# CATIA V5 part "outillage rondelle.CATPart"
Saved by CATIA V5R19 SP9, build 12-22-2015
Part number: outillage rondelle
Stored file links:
  D:\filesystem\herve.bezard\Telechargements\fausse table rondelle\outillage rondelle.CATPart
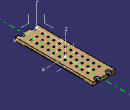
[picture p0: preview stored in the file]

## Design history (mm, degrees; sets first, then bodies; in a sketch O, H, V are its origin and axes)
AxisSystem1: origin (0, 0, 0), X (1, 0, 0), Y (0, 1, 0), Z (0, 0, 1)
AxisSystem2: origin (-48.5, -174, 0), X (1, 0, 0), Y (0, 1, 0), Z (0, 0, 1)
Set1 "GEOCN"
  Point1: (0, -3, 0), relative to vertex [face of Pad1 from Sketch1.L3 | face of Pad1 from Sketch1.L2 | start face of Pad1], in AxisSystem1
Body1 (main body)
  Sketch1 on XY plane of AxisSystem1, origin (0, 0, 0), H (1, 0, 0), V (0, 1, 0)
    line L1 (48.5, 171) -> (48.5, -171)
    line L2 (48.5, -171) -> (-48.5, -171)
    line L3 (-48.5, -171) -> (-48.5, 171)
    line L4 (-48.5, 171) -> (48.5, 171)
    distance L3 L1 = 97
    distance L4 L2 = 342
    vertical: L1 V, L3 V
    horizontal: L2 H, L4 H
    equidistance: L1 L3 O, L2 L4 O
  Pad1: profile Sketch1, direction (0, 0, 1), length 15
  Sketch2 on XY plane of AxisSystem1, origin (0, 0, 0), H (1, 0, 0), V (0, 1, 0)
    construction line L1 (-25, 173) -> (-25, 165)
    point P2 (-25, 165)
    line L2 (-21.9, 173) -> (-21.9, 165)
    line L3 (-28.1, 165) -> (-28.1, 173)
    arc A1 centre (-25, 165) radius 3.1 from (-21.9, 165) to (-28.1, 165) cw
    arc A2 centre (-25, 173) radius 3.1 from (-28.1, 173) to (-21.9, 173) cw
    construction line L4 (25, 173) -> (25, 165)
    point P8 (25, 165)
    line L5 (28.1, 173) -> (28.1, 165)
    line L6 (21.9, 165) -> (21.9, 173)
    arc A3 centre (25, 165) radius 3.1 from (28.1, 165) to (21.9, 165) cw
    arc A4 centre (25, 173) radius 3.1 from (21.9, 173) to (28.1, 173) cw
    construction line L7 (-25, -165) -> (-25, -173)
    point P13 (-25, -165)
    line L8 (-21.9, -165) -> (-21.9, -173)
    line L9 (-28.1, -173) -> (-28.1, -165)
    arc A5 centre (-25, -173) radius 3.1 from (-21.9, -173) to (-28.1, -173) cw
    arc A6 centre (-25, -165) radius 3.1 from (-28.1, -165) to (-21.9, -165) cw
    construction line L10 (25, -165) -> (25, -173)
    point P19 (25, -165)
    line L11 (28.1, -165) -> (28.1, -173)
    line L12 (21.9, -173) -> (21.9, -165)
    arc A7 centre (25, -173) radius 3.1 from (28.1, -173) to (21.9, -173) cw
    arc A8 centre (25, -165) radius 3.1 from (21.9, -165) to (28.1, -165) cw
    reference projected line E1 through (0, 0) direction (0, 1) from edge [YZ plane of AxisSystem1 | XY plane of AxisSystem1]
    reference projected line E2 through (0, 0) direction (0, 1) from edge [YZ plane of AxisSystem1 | XY plane of AxisSystem1]
    reference projected line E3 through (0, 0) direction (0, 1) from edge [YZ plane of AxisSystem1 | XY plane of AxisSystem1]
    reference projected line E4 through (0, 0) direction (0, 1) from edge [YZ plane of AxisSystem1 | XY plane of AxisSystem1]
    reference intersected line E5 (-48.5, 171) -> (48.5, 171) from face of Pad1 from Sketch1.L4
    reference intersected line E6 (-48.5, 171) -> (48.5, 171) from face of Pad1 from Sketch1.L4
    reference intersected line E7 (48.5, -171) -> (-48.5, -171) from face of Pad1 from Sketch1.L2
    reference intersected line E8 (48.5, -171) -> (-48.5, -171) from face of Pad1 from Sketch1.L2
    distance L1 L2 = 3.1
    distance L4 L5 = 3.1
    distance L7 L8 = 3.1
    distance L10 L11 = 3.1
    distance L7 E1 = 25
    distance L10 E2 = 25
    distance L1 E3 = 25
    distance L4 E4 = 25
    distance P2 E5 = 6
    distance P8 E6 = 6
    distance P19 E7 = 6
    distance P13 E8 = 6
    length L7 = 8
    length L10 = 8
    length L1 = 8
    length L4 = 8
    vertical: L1 V, L4 V, L7 V, L10 V
    tangency: A1 L2, A2 L2, A1 L3, A2 L3, A3 L5, A4 L5, A3 L6, A4 L6, A5 L8, A6 L8, A5 L9, A6 L9, A7 L11, A8 L11, A7 L12, A8 L12
  Pocket1: profile Sketch2, direction (0, 0, -1), through (limit type 6)
  Sketch3 on end face of Pad1, origin (0, 0, 15), H (1, 0, 0), V (0, 1, 0)
    construction line L1 (-25, 173) -> (-25, 165)
    point P2 (-25, 165)
    line L2 (-15, 173) -> (-15, 165)
    line L3 (-35, 165) -> (-35, 173)
    arc A1 centre (-25, 165) radius 10 from (-15, 165) to (-35, 165) cw
    arc A2 centre (-25, 173) radius 10 from (-35, 173) to (-15, 173) cw
    construction line L4 (25, 173) -> (25, 165)
    point P8 (25, 165)
    line L5 (35, 173) -> (35, 165)
    line L6 (15, 165) -> (15, 173)
    arc A3 centre (25, 165) radius 10 from (35, 165) to (15, 165) cw
    arc A4 centre (25, 173) radius 10 from (15, 173) to (35, 173) cw
    construction line L7 (25, -165) -> (25, -173)
    point P13 (25, -165)
    line L8 (35, -165) -> (35, -173)
    line L9 (15, -173) -> (15, -165)
    arc A5 centre (25, -173) radius 10 from (35, -173) to (15, -173) cw
    arc A6 centre (25, -165) radius 10 from (15, -165) to (35, -165) cw
    construction line L10 (-25, -165) -> (-25, -173)
    point P19 (-25, -165)
    line L11 (-15, -165) -> (-15, -173)
    line L12 (-35, -173) -> (-35, -165)
    arc A7 centre (-25, -173) radius 10 from (-15, -173) to (-35, -173) cw
    arc A8 centre (-25, -165) radius 10 from (-35, -165) to (-15, -165) cw
    reference projected point E1 (-25, 165) from axis of face of Pocket1 from Sketch2.A1
    reference projected point E2 (25, 165) from axis of face of Pocket1 from Sketch2.A3
    reference projected point E3 (-25, -165) from axis of face of Pocket1 from Sketch2.A6
    reference projected point E4 (25, -165) from axis of face of Pocket1 from Sketch2.A8
    distance L1 L2 = 10
    distance L4 L5 = 10
    distance L7 L8 = 10
    distance L10 L11 = 10
    length L7 = 8
    length L10 = 8
    length L4 = 8
    length L1 = 8
    vertical: L1 V, L4 V, L7 V, L10 V
    tangency: A1 L2, A2 L2, A1 L3, A2 L3, A3 L5, A4 L5, A3 L6, A4 L6, A5 L8, A6 L8, A5 L9, A6 L9, A7 L11, A8 L11, A7 L12, A8 L12
    coincidence: P2 E1, P8 E2, P19 E3, P13 E4
  Pocket2: profile Sketch3, direction (0, 0, -1), up to start face of Pad1, offset -7
  Sketch4 on XY plane of AxisSystem1, origin (0, 0, 0), H (1, 0, 0), V (0, 1, 0)
    construction line L1 (-27.9, -125) -> (-22.1, -125)
    line L2 (-27.9, -119.95) -> (-22.1, -119.95)
    line L3 (-22.1, -130.05) -> (-27.9, -130.05)
    arc A1 centre (-22.1, -125) radius 5.05 from (-22.1, -119.95) to (-22.1, -130.05) cw
    arc A2 centre (-27.9, -125) radius 5.05 from (-27.9, -130.05) to (-27.9, -119.95) cw
    point P7 (-25, -125)
    point P8 (-27.8868, -130)
    point P9 (-22.1132, -130)
    point P10 (-19.2265, -125)
    point P11 (-22.1132, -120)
    point P12 (-27.8868, -120)
    point P13 (-30.7735, -125)
    point P14 (-25, -130)
    construction line L4 (-27.8868, -130) -> (-22.1132, -130)
    construction line L5 (-22.1132, -130) -> (-19.2265, -125)
    construction line L6 (-19.2265, -125) -> (-22.1132, -120)
    construction line L7 (-22.1132, -120) -> (-27.8868, -120)
    construction line L8 (-27.8868, -120) -> (-30.7735, -125)
    construction line L9 (-30.7735, -125) -> (-27.8868, -130)
    construction line L10 (-25, -125) -> (-25, -130)
    construction circle A3 centre (-25, -125) radius 5.7735
    construction arc A4 centre (-27.8868, -120) radius 5.7735 from (-22.1132, -120) to (-30.7735, -125) cw
    construction arc A5 centre (-22.1132, -130) radius 5.7735 from (-19.2265, -125) to (-27.8868, -130) ccw
    reference projected line E1 through (0, 0) direction (0, 1) from edge [YZ plane of AxisSystem1 | XY plane of AxisSystem1]
    reference projected line E2 through (0, 0) direction (1, 0) from edge [XY plane of AxisSystem1 | ZX plane of AxisSystem1]
    distance L1 L2 = 5.05
    distance L4 L7 = 10
    length L1 = 5.8
    length L7 = 5.7735 (reference)
    distance E1 P7 = 25
    distance E2 P7 = 125
    horizontal: L1 H
    tangency: A1 L2, A2 L2, A1 L3, A2 L3
    vertical: L10 V
    coincidence: A3 P8, A3 P9, A3 P10, A3 P11, A3 P12, A3 P13, A4 P7, A5 P7
    midpoint: P14 L4, L1 P7
    parallelism: L4 L7
  Pocket3: profile Sketch4, direction (0, 0, 1), length 6
  Sketch5 on XY plane of AxisSystem1, origin (0, 0, 0), H (1, 0, 0), V (0, 1, 0)
    point P1 (-25, -125)
    reference projected line E1 through (0, 0) direction (0, 1) from edge [YZ plane of AxisSystem1 | XY plane of AxisSystem1]
    reference projected line E2 through (0, 0) direction (1, 0) from edge [XY plane of AxisSystem1 | ZX plane of AxisSystem1]
    distance P1 E1 = 25
    distance P1 E2 = 125
  Hole1: placed by Sketch5, at (-25, -125, 0) direction (0, 0, -1), diameter 6.2, through (limit type 6)
  Sketch6 on end face of Pad1, origin (-14.3209, -81.386, 15), H (1, 0, 0), V (0, 1, 0)
    point P1 (-10.6791, -43.614)
    reference projected point E1 (-10.6791, -43.614) from axis of face of Hole1
    coincidence: P1 E1
  Hole2: placed by Sketch6, at (-25, -125, 15) direction (0, 0, -1), diameter 8, depth 3
  RectPattern1: of Pocket3, Hole1, Hole2, direction 1 instances 3, spacing 25, along X axis, direction 2 instances 11, spacing 25, along Y axis
  Sketch7 on end face of Pad1, origin (0, 0, 15), H (1, 0, 0), V (0, 1, 0)
    construction line L1 (-53.5, 125) -> (-53.5, -125)
    point P1 (-53.5, 125)
    point P2 (-53.5, -125)
    line L2 (-47.5, 125) -> (-47.5, -125)
    line L3 (-59.5, -125) -> (-59.5, 125)
    arc A1 centre (-53.5, -125) radius 6 from (-47.5, -125) to (-59.5, -125) cw
    arc A2 centre (-53.5, 125) radius 6 from (-59.5, 125) to (-47.5, 125) cw
    reference intersected line E1 (-48.5, -171) -> (-48.5, 171) from face of Pad1 from Sketch1.L3
    reference projected line E2 through (0, 0) direction (1, 0) from edge [XY plane of AxisSystem1 | ZX plane of AxisSystem1]
    distance L1 L2 = 6
    distance L1 E1 = 5
    length L1 = 250
    vertical: L1 V
    tangency: A1 L2, A2 L2, A1 L3, A2 L3
    symmetry: P1 P2 E2
  Pocket4: profile Sketch7, direction (0, 0, -1), length 4
  Sketch8 on XY plane of AxisSystem1, origin (0, 0, 0), H (1, 0, 0), V (0, 1, 0)
    construction line L1 (52.5, 125) -> (52.5, -125)
    point P1 (52.5, 125)
    point P2 (52.5, -125)
    line L2 (58.5, 125) -> (58.5, -125)
    line L3 (46.5, -125) -> (46.5, 125)
    arc A1 centre (52.5, -125) radius 6 from (58.5, -125) to (46.5, -125) cw
    arc A2 centre (52.5, 125) radius 6 from (46.5, 125) to (58.5, 125) cw
    reference intersected line E1 (48.5, 171) -> (48.5, -171) from face of Pad1 from Sketch1.L1
    reference projected line E2 through (0, 0) direction (1, 0) from edge [XY plane of AxisSystem1 | ZX plane of AxisSystem1]
    distance L1 L2 = 6
    distance L1 E1 = 4
    length L1 = 250
    vertical: L1 V
    tangency: A1 L2, A2 L2, A1 L3, A2 L3
    symmetry: P2 P1 E2
  Pocket5: profile Sketch8, direction (0, 0, 1), length 4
